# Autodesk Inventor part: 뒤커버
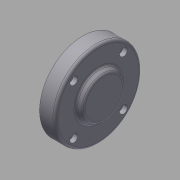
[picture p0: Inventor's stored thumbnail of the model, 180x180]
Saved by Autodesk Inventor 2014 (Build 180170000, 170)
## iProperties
Company: 한국ATC센터
Created: 2015-12
Part Number: 뒤커버
Document SubType Name: Modeling
Designer: mdu
Density: 2.71 g/cm^3
Mass: 105.756 g
Surface Area: 115.002 cm^2
Volume: 39.0244 cm^3
Material: 알루미늄 6061
Appearance: 알루미늄 - 평지
Author: mdu
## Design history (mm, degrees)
sketch "스케치1"
  geometry: L1 (-10.5, 0)-(10.5, 0); L2 (10.5, 0)-(10.5, 22.5); L3 (10.5, 22.5)-(5.5, 22.5); L4 (5.5, 22.5)-(5.5, 32.5); L5 (5.5, 32.5)-(-6.5, 32.5); L6 (-6.5, 32.5)-(-6.5, 17.5); L7 (-6.5, 17.5)-(-10.5, 15.191); L8 (-10.5, 15.191)-(-10.5, 0); 2 further points
  constraints: 16 end point, 3 parallel, 3 perpendicular, 1 coincident, 1 horizontal, 1 midpoint
  dimensions: "d0" = 21 distance of L1.start L1.end; "d1" = 65 diameter of L5 L1; "d2" = 45 diameter of L3 L1; "d3" = 35 diameter of L6.end L1; "d4" = 120 deg angle of L7 L6; "d5" = 12 distance of L4.end L5.end; "d6" = 5 distance of L2.end L3.end
revolve "회전1" sketch "스케치1" stored, may be unused: angle "d7" = 90 deg
sketch "스케치2"
  geometry: L1 (0, 0)-(32.5, 0); L2 (0, 0)-(18.738, 18.738); 1 further point
  constraints: 4 end point, 1 horizontal, 1 horizontal alignment, 1 other
  dimensions: "d8" = 45 deg angle of L1 L2; "d9" = 26.5 distance of L1.start L2.end
hole "구멍1" sketch "스케치2" at (18.738, 18.738) diameter "d10" = 3.4; stored, may be unused: countersink angle "d14" = 90 deg, drill point angle "d16" = 118 deg; dims "d11" = 6, "d12" = 6, "d13" = 3.3, "d15" = 8
fillet "모깎기1" dims "d20" = 2
hole "구멍2" diameter "d23" = 15; stored, may be unused: countersink angle "d27" = 90 deg, drill point angle "d29" = 0 deg; dims "d21" = 10, "d22" = 10, "d24" = 6, "d25" = 35, "d26" = 11, "d28" = 14
chamfer "모따기1" distance "d39" = 1; stored, may be unused: second distance "d40" = 2, angle "d41" = 45 deg
fillet "모깎기2" dims "d42" = 0.3
chamfer "모따기3" distance "d57" = 1; stored, may be unused: second distance "d58" = 2, angle "d59" = 45 deg
fillet "모깎기4" dims "d60" = 1
node "솔리드1"
pattern_circular "원형 패턴1" dims angle "d18" = 360 deg
